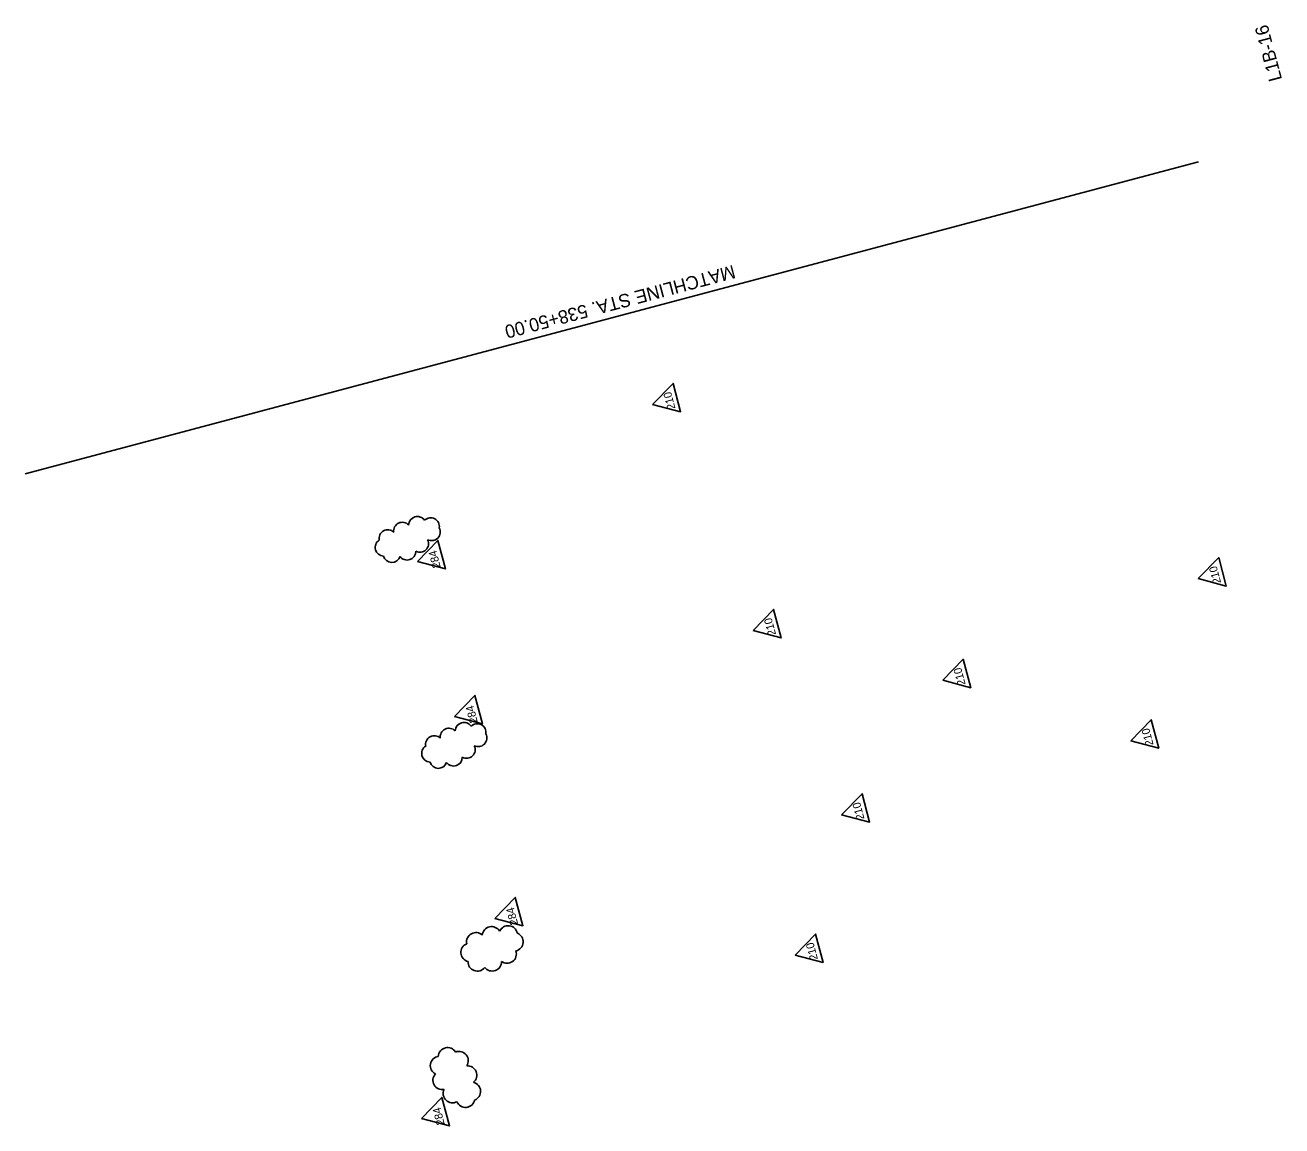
# Model space of a CAD drawing. Extents: x 930124 to 931186, y 628803 to 630086.
# Drawn here: x 930124 to 930878, y 629426 to 630086 of the extents above; entities that cross this region are included whole.
import ezdxf

# ---------------------------------------------------------------- set-up
doc = ezdxf.new("R2010")
doc.units = 0
for name, color, linetype in [('Cloud_dp', 7, 'Continuous'), ('MatchLines_dp', 7, 'Continuous'), ('TextShtNo', 7, 'Continuous')]:
    doc.layers.add(name, color=color, linetype=linetype)

msp = doc.modelspace()

# ---------------------------------------------------------------- linework, layer by layer
at = {"layer": 'Cloud_dp'}
for points in [[(930500.36, 629859), (930517.12, 629854.54), (930512.58, 629871.6)], [(930359.33, 629764.82), (930376.08, 629760.36), (930371.55, 629777.42)], [(930827.55, 629754.51), (930844.31, 629750.05), (930839.77, 629767.11)], [(930560.71, 629723.42), (930577.47, 629718.96), (930572.93, 629736.02)], [(930674.33, 629693.58), (930691.08, 629689.12), (930686.55, 629706.18)], [(930381.56, 629671.84), (930398.32, 629667.38), (930393.78, 629684.44)], [(930787.06, 629657.28), (930803.81, 629652.82), (930799.28, 629669.88)], [(930613.7, 629612.9), (930630.46, 629608.44), (930625.93, 629625.5)], [(930405.8, 629550.79), (930422.55, 629546.33), (930418.02, 629563.39)], [(930585.8, 629528.79), (930602.56, 629524.33), (930598.02, 629541.38)], [(930361.73, 629430.82), (930378.49, 629426.36), (930373.95, 629443.42)]]:
    msp.add_lwpolyline(points, close=True, dxfattribs=at)
for centre, radius, start, end in [((930350.26, 629783.1), 5.21, 43.31257, 188.31257), ((930359.27, 629786.57), 5.21, 33.91184, 178.91184), ((930367.29, 629785.82), 5.21, 350.30948, 135.30948), ((930341.5, 629778.59), 5.21, 46.10802, 191.10802), ((930367.83, 629782.49), 5.21, 243.02408, 28.02408), ((930339.18, 629773.19), 5.21, 122.47753, 267.47753), ((930360.8, 629775.52), 5.21, 241.49045, 26.49045), ((930343.95, 629769.46), 5.21, 196.32715, 341.32715), ((930353.1, 629770.85), 5.21, 216.02366, 1.02366), ((930387.19, 629663.06), 5.21, 33.91184, 178.91184), ((930369.42, 629655.08), 5.21, 46.10802, 191.10802), ((930378.19, 629659.59), 5.21, 43.31257, 188.31257), ((930395.22, 629662.31), 5.21, 350.30948, 135.30948), ((930395.75, 629658.98), 5.21, 243.02408, 28.02408), ((930367.1, 629649.68), 5.21, 122.47753, 267.47753), ((930388.72, 629652.01), 5.21, 241.49045, 26.49045), ((930381.03, 629647.34), 5.21, 216.02366, 1.02366), ((930371.88, 629645.95), 5.21, 196.32715, 341.32715), ((930394.38, 629536.68), 5.59, 46.32134, 191.32134), ((930403.81, 629540.26), 5.59, 30.22482, 175.22482), ((930413.75, 629540.8), 5.59, 11.04867, 156.04867), ((930417.14, 629536.7), 5.58, 282.86329, 67.86329), ((930390.96, 629530.38), 5.59, 111.60535, 256.60535), ((930395.25, 629524.76), 5.59, 178.12595, 323.12595), ((930404.19, 629524.77), 5.59, 216.92297, 1.92297), ((930413.09, 629529.46), 5.59, 233.72032, 18.72032), ((930377.43, 629467.7), 5.59, 31.59693, 176.59693), ((930372.64, 629462.5), 5.59, 98.11754, 243.11754), ((930384.22, 629465.42), 5.59, 326.31292, 111.31292), ((930374.2, 629453.7), 5.59, 136.91455, 281.91455), ((930389.38, 629456.76), 5.59, 310.21641, 95.21641), ((930391.64, 629447.06), 5.59, 291.04025, 76.04025), ((930380.36, 629445.75), 5.59, 153.7119, 298.7119), ((930388.19, 629443.02), 5.58, 202.85487, 347.85487)]:
    msp.add_arc(centre, radius, start, end, dxfattribs=at)
at = {"layer": 'MatchLines_dp'}
msp.add_lwpolyline([(930827.71, 630004.46), (930472.01, 629909.88), (930124.1, 629817.37)], dxfattribs=at)

# ---------------------------------------------------------------- texts
at = {"layer": 'Cloud_dp'}
for s, p in [('210', (930514.08, 629856.59)), ('284', (930373.29, 629761.47)), ('210', (930841.27, 629752.1)), ('210', (930574.43, 629721.01)), ('210', (930688.05, 629691.17)), ('284', (930395.53, 629668.49)), ('210', (930800.78, 629654.87)), ('210', (930627.42, 629610.49)), ('284', (930419.76, 629547.44)), ('210', (930599.52, 629526.37)), ('284', (930375.7, 629427.47))]:
    msp.add_text(s, height=4.799, rotation=104.89046, dxfattribs=at).set_placement(p)
at = {"layer": 'MatchLines_dp'}
msp.add_text('MATCHLINE STA. 538+50.00', height=8, rotation=194.89045, dxfattribs=at).set_placement((930548.67, 629942.68))
at = {"layer": 'TextShtNo'}
msp.add_text('L1B-16', height=8, rotation=104.89045, dxfattribs=at).set_placement((930877.89, 630053.89))

doc.saveas('drawing.dxf')
